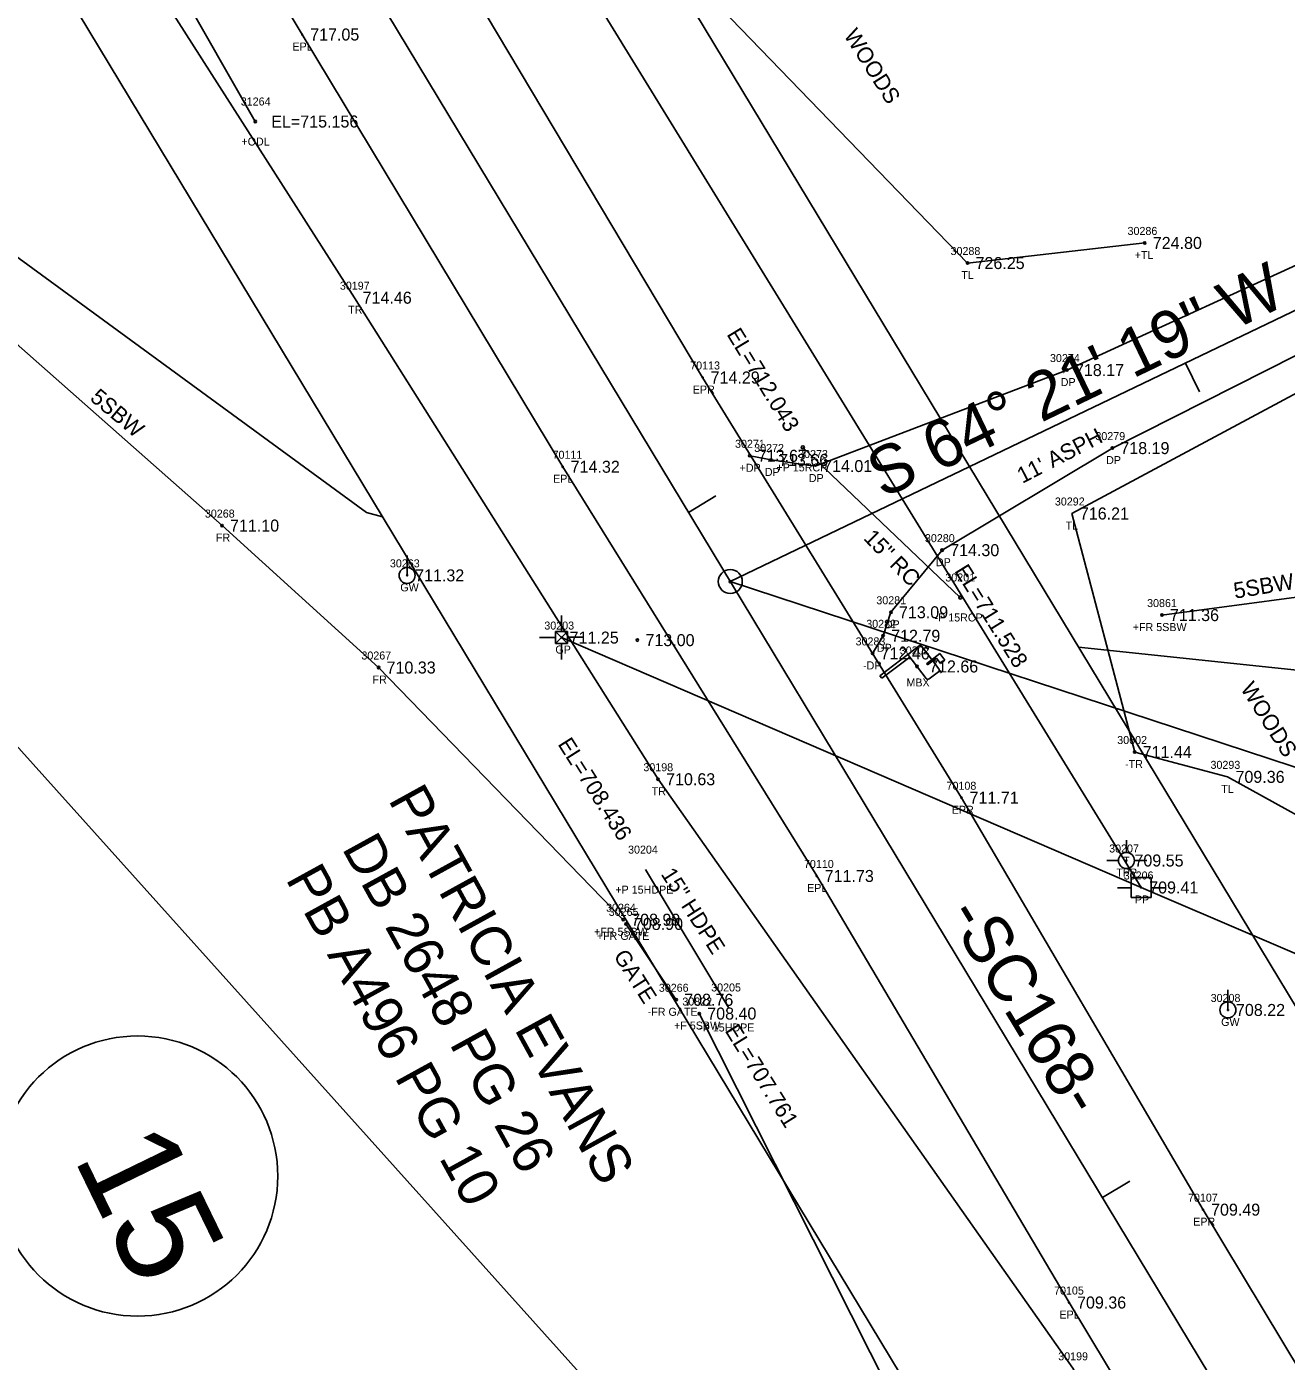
# Model space of a CAD drawing. Extents: x 1375131 to 1378678, y 999028 to 1004053.
# Drawn here: x 1377107.8 to 1377265.2, y 1001844.5 to 1002011.2 of the extents above; entities that cross this region are included whole.
import ezdxf

# ---------------------------------------------------------------- set-up
doc = ezdxf.new("R2010")
doc.units = 0
for name, color, linetype in [('RD_EX_BldgApp', 7, 'Continuous'), ('RD_EX_BldgApp_txCode', 7, 'Continuous'), ('RD_EX_DR_Pipe', 7, 'Continuous'), ('RD_EX_DR_Pipe_txCode', 7, 'Continuous'), ('RD_EX_Driveway', 7, 'Continuous'), ('RD_EX_Driveway_txCode', 7, 'Continuous'), ('RD_EX_DV_Prop', 7, 'Continuous'), ('RD_EX_DV_TX_Prop(Owner ID)', 7, 'Continuous'), ('RD_EX_Fence_Other', 7, 'Continuous'), ('RD_EX_Fence_Other_txCode', 7, 'Continuous'), ('RD_EX_H2O', 7, 'Continuous'), ('RD_EX_H2O_txCode', 7, 'Continuous'), ('RD_EX_Road', 7, 'Continuous'), ('RD_EX_Road_txCode', 7, 'Continuous'), ('RD_EX_RW', 7, 'Continuous'), ('RD_EX_SU_Elec', 7, 'Continuous'), ('RD_EX_TX_BldgApp_ELEV', 7, 'Continuous'), ('RD_EX_TX_Driveway_ELEV', 7, 'Continuous'), ('RD_EX_TX_Fence_Other_ELEV', 7, 'Continuous'), ('RD_EX_TX_H2O_ELEV', 7, 'Continuous'), ('RD_EX_TX_Road_ELEV', 7, 'Continuous'), ('RD_EX_TX_UT_ELEV', 7, 'Continuous'), ('RD_EX_TX_VEG_ELEV', 7, 'Continuous'), ('RD_EX_UT', 7, 'Continuous'), ('RD_EX_UT_txCode', 7, 'Continuous'), ('RD_EX_VEG', 7, 'Continuous'), ('RD_EX_VEG_txCode', 7, 'Continuous'), ('RD_HC_Cl', 7, 'Continuous'), ('RD_HC_Data', 7, 'Continuous'), ('RD_HC_Data_Tic', 7, 'Continuous'), ('RD_HC_Survey_ELEV', 7, 'Continuous'), ('RD_SMD_Locator', 7, 'Continuous'), ('RD_TX_Drainage', 7, 'Continuous'), ('RD_TX_Misc2', 7, 'Continuous'), ('RD_TX_Pipe_ElevEX', 7, 'Continuous')]:
    doc.layers.add(name, color=color, linetype=linetype)

msp = doc.modelspace()

# ---------------------------------------------------------------- linework, layer by layer
at = {"layer": 'RD_EX_BldgApp'}
for p, q in [((1377217.91, 1001932.77), (1377214.39, 1001930.11)), ((1377217.91, 1001932.77), (1377219.3, 1001933.82)), ((1377220.19, 1001929.75), (1377217.91, 1001932.77)), ((1377219.65, 1001933.77), (1377221.78, 1001930.95)), ((1377220.22, 1001931.6), (1377221.89, 1001932.87)), ((1377221.89, 1001932.87), (1377222.51, 1001932.05)), ((1377218.16, 1001932.43), (1377214.64, 1001929.78)), ((1377220.33, 1001931.45), (1377220.22, 1001931.6)), ((1377221.47, 1001932.31), (1377220.33, 1001931.45)), ((1377221.97, 1001931.64), (1377221.47, 1001932.31)), ((1377222.51, 1001932.05), (1377221.97, 1001931.64)), ((1377214.39, 1001930.11), (1377214.64, 1001929.78)), ((1377221.73, 1001930.6), (1377220.54, 1001929.7)), ((1377221.73, 1001930.6), (1377221.93, 1001930.75)), ((1377221.93, 1001930.75), (1377222.08, 1001930.56)), ((1377222.08, 1001930.56), (1377221.98, 1001930.48))]:
    msp.add_line(p, q, dxfattribs=at)
for centre, start, end in [((1377219.45, 1001933.62), 37.0668, 127.0668), ((1377221.58, 1001930.8), 307.0668, 37.0668), ((1377220.39, 1001929.9), 217.0668, 307.0668)]:
    msp.add_arc(centre, 0.25, start, end, dxfattribs=at)
at = {"layer": 'RD_EX_DR_Pipe'}
for p, q in [((1377204.78, 1001958.63), (1377224.45, 1001939.88)), ((1377185.11, 1001905.88), (1377195.49, 1001888.66))]:
    msp.add_line(p, q, dxfattribs=at)
at = {"layer": 'RD_EX_Driveway'}
for points in [[(1377198.42, 1001957.52), (1377200.81, 1001957.06), (1377206.31, 1001956.3), (1377237.77, 1001968.29), (1377271.95, 1001983.94), (1377310.88, 1002003.15)], [(1377315.4, 1001995.58), (1377274.11, 1001974.03), (1377243.44, 1001958.54), (1377222.18, 1001945.79), (1377215.79, 1001938.03), (1377214.81, 1001935.09), (1377213.5, 1001932.9)]]:
    msp.add_lwpolyline(points, dxfattribs=at)
at = {"layer": 'RD_EX_DV_Prop'}
msp.add_line((1376947.76, 1002098.6), (1377150.28, 1001950.48), dxfattribs=at)
for points in [[(1377150.28, 1001950.48), (1377152.29, 1001949.95)], [(1377239.22, 1001933.68), (1377316.8, 1001925.5), (1377415.78, 1001865), (1377549.86, 1001831.61)]]:
    msp.add_lwpolyline(points, dxfattribs=at)
at = {"layer": 'RD_EX_DV_TX_Prop(Owner ID)'}
msp.add_circle((1377121.69, 1001867.6), 17.5, dxfattribs=at)
at = {"layer": 'RD_EX_Fence_Other'}
msp.add_line((1377182.68, 1001899.1), (1377188.96, 1001889.62), dxfattribs=at)
for points in [[(1377491.06, 1002061.52), (1377478.6, 1002062.15), (1377445.25, 1002038.31), (1377440.22, 1002014.81), (1377436.73, 1001992.25), (1377399.99, 1001998.37), (1377304.37, 1001966.22), (1377283.11, 1001947.94), (1377275.82, 1001941.17), (1377249.63, 1001937.68)], [(1377182.34, 1001899.62), (1377151.78, 1001931.13), (1377132.23, 1001948.86), (1377093.24, 1001983.33), (1377067.17, 1002003.69)], [(1377191.84, 1001887.9), (1377236.93, 1001798.52), (1377265.75, 1001745.48), (1377304.79, 1001682.79)]]:
    msp.add_lwpolyline(points, dxfattribs=at)
at = {"layer": 'RD_EX_H2O'}
msp.add_lwpolyline([(1377136.38, 1001999.34), (1377116.95, 1002033.41), (1377090.35, 1002075.98), (1377065.42, 1002117.59), (1377038.3, 1002163.03), (1377017.87, 1002196.37), (1376989.72, 1002244.93), (1376963.62, 1002288.23), (1376935.26, 1002334.03)], dxfattribs=at)
at = {"layer": 'RD_EX_Road'}
for points in [[(1377350.34, 1001708.26), (1377317.92, 1001758.89), (1377286.96, 1001809.89), (1377254.77, 1001863.4), (1377224.6, 1001914.86), (1377192.26, 1001967.36), (1377160.97, 1002019.84), (1377129.72, 1002070.66), (1377099.39, 1002121.71), (1377064.16, 1002179.08), (1377033.49, 1002231.09), (1377014.7, 1002262.97), (1377013.31, 1002264.91)], [(1377330.92, 1001696.38), (1377301.06, 1001747.92), (1377269.09, 1001800.22), (1377238.03, 1001851.8), (1377206.51, 1001905.09), (1377174.78, 1001956.21), (1377142.24, 1002010.21), (1377112.37, 1002059.86), (1377081.07, 1002112.14), (1377047.75, 1002166.27), (1377015.04, 1002220.7), (1376995.39, 1002252.52), (1376994.75, 1002253.91)]]:
    msp.add_lwpolyline(points, dxfattribs=at)
at = {"layer": 'RD_EX_RW'}
for p, q in [((1377036.35, 1002269.57), (1377580.54, 1001368.57)), ((1376979.85, 1002235.45), (1377524.04, 1001334.45))]:
    msp.add_line(p, q, dxfattribs=at)
at = {"layer": 'RD_EX_SU_Elec'}
for points in [[(1376932.6, 1002329.07), (1377163.28, 1002039.96), (1377247.04, 1001903.65)], [(1377174.65, 1001934.87), (1377247.04, 1001903.65), (1377437.44, 1001822.1), (1377567.31, 1002066.68)]]:
    msp.add_lwpolyline(points, dxfattribs=at)
at = {"layer": 'RD_EX_UT'}
for p, q in [((1377155.35, 1001942.64), (1377155.35, 1001945.14)), ((1377174.65, 1001935.62), (1377174.65, 1001937.62)), ((1377173.88, 1001934.9), (1377171.88, 1001934.9)), ((1377175.4, 1001935.62), (1377173.9, 1001934.12)), ((1377173.9, 1001935.62), (1377175.4, 1001934.12)), ((1377175.4, 1001935.62), (1377173.9, 1001935.62)), ((1377173.9, 1001935.62), (1377173.9, 1001934.12)), ((1377175.4, 1001934.12), (1377175.4, 1001935.62)), ((1377175.4, 1001934.91), (1377177.41, 1001934.91)), ((1377173.9, 1001934.12), (1377175.4, 1001934.12)), ((1377174.65, 1001934.12), (1377174.65, 1001932.12)), ((1377245.2, 1001909.55), (1377245.2, 1001908.02)), ((1377242.74, 1001907.03), (1377244.2, 1001907.03)), ((1377246.2, 1001907.03), (1377247.74, 1001907.03)), ((1377248.29, 1001904.9), (1377245.79, 1001904.9)), ((1377245.79, 1001904.9), (1377245.79, 1001902.4)), ((1377248.29, 1001902.4), (1377248.29, 1001904.9)), ((1377244.07, 1001903.62), (1377245.81, 1001903.62)), ((1377248.25, 1001903.62), (1377250.07, 1001903.62)), ((1377245.79, 1001902.4), (1377248.29, 1001902.4)), ((1377257.88, 1001888.35), (1377257.88, 1001890.85))]:
    msp.add_line(p, q, dxfattribs=at)
for centre in [(1377155.35, 1001942.64), (1377245.2, 1001907.02), (1377257.88, 1001888.35)]:
    msp.add_circle(centre, 1, dxfattribs=at)
at = {"layer": 'RD_EX_VEG'}
for points in [[(1377227.27, 1001786.89), (1377002.39, 1002037.45), (1376937.65, 1002151.76), (1376893.73, 1002289.53), (1376925.29, 1002323.56)], [(1376925.29, 1002323.56), (1376964.39, 1002271.55), (1376999.6, 1002220.98), (1377033.75, 1002161.52), (1377072.45, 1002098.21), (1377110.65, 1002037.08), (1377148.79, 1001977.33), (1377186.7, 1001917.17), (1377238.51, 1001843.58), (1377265.98, 1001789.91), (1377290.89, 1001746.87), (1377322.19, 1001689.75), (1377357.87, 1001632.38)], [(1377534.01, 1002073.13), (1377547.87, 1002047.96), (1377449.99, 1001867.71), (1377414.83, 1001847.8), (1377322.94, 1001881.51), (1377257.82, 1001917.47), (1377246.23, 1001920.57)], [(1377200.2, 1002035.7), (1377185.96, 1002022.4), (1377225.35, 1001981.66), (1377247.49, 1001984.17)], [(1377293.69, 1001980), (1377238.38, 1001950.37), (1377246.23, 1001920.57)]]:
    msp.add_lwpolyline(points, dxfattribs=at)
at = {"layer": 'RD_HC_Cl'}
for p, q in [((1377008.1, 1002252.51), (1377552.29, 1001351.51)), ((1377284.22, 1001984.36), (1377195.72, 1001941.87))]:
    msp.add_line(p, q, dxfattribs=at)
at = {"layer": 'RD_HC_Data'}
msp.add_line((1377195.72, 1001941.87), (1377336.15, 1001895.74), dxfattribs=at)
for radius in [1.5, 0.141]:
    msp.add_circle((1377195.72, 1001941.87), radius, dxfattribs=at)
at = {"layer": 'RD_HC_Data_Tic'}
for p, q in [((1377252.58, 1001969.17), (1377254.32, 1001965.56)), ((1377190.51, 1001950.5), (1377193.93, 1001952.57)), ((1377242.21, 1001864.9), (1377245.63, 1001866.97))]:
    msp.add_line(p, q, dxfattribs=at)
at = {"layer": 'RD_SMD_Locator'}
for centre, radius in [((1377142.24, 1002010.21), 0.075), ((1377136.38, 1001999.34), 0.15), ((1377247.49, 1001984.17), 0.15), ((1377225.35, 1001981.66), 0.15), ((1377237.77, 1001968.29), 0.15), ((1377192.26, 1001967.36), 0.075), ((1377198.15, 1001957.58), 0.15), ((1377204.78, 1001958.63), 0.2), ((1377243.44, 1001958.54), 0.15), ((1377174.78, 1001956.21), 0.075), ((1377200.81, 1001957.06), 0.15), ((1377132.23, 1001948.86), 0.15), ((1377222.18, 1001945.79), 0.15), ((1377155.35, 1001942.64), 0.075), ((1377195.72, 1001941.87), 0.075), ((1377224.45, 1001939.88), 0.2), ((1377215.79, 1001938.03), 0.15), ((1377249.63, 1001937.68), 0.15), ((1377174.65, 1001934.87), 0.075), ((1377184.12, 1001934.55), 0.15), ((1377214.81, 1001935.09), 0.15), ((1377213.49, 1001932.89), 0.15), ((1377151.78, 1001931.13), 0.15), ((1377219.05, 1001931.26), 0.15), ((1377246.23, 1001920.57), 0.15), ((1377186.7, 1001917.17), 0.15), ((1377224.6, 1001914.86), 0.075), ((1377245.2, 1001907.02), 0.075), ((1377206.51, 1001905.09), 0.075), ((1377247.04, 1001903.65), 0.075), ((1377182.34, 1001899.62), 0.15), ((1377182.68, 1001899.1), 0.15), ((1377188.96, 1001889.62), 0.15), ((1377191.84, 1001887.9), 0.15), ((1377257.88, 1001888.35), 0.075), ((1377254.77, 1001863.4), 0.075), ((1377238.03, 1001851.8), 0.075)]:
    msp.add_circle(centre, radius, dxfattribs=at)

# ---------------------------------------------------------------- texts
at = {"layer": 'RD_EX_BldgApp_txCode'}
for s, p in [('30202', (1377216.89, 1001932.76)), ('MBX', (1377217.72, 1001928.76))]:
    msp.add_text(s, height=1, dxfattribs=at).set_placement(p)
at = {"layer": 'RD_EX_DR_Pipe_txCode'}
for s, p in [('+P 15RCP', (1377201.48, 1001955.63)), ('30201', (1377222.58, 1001941.88)), ('-P 15RCP', (1377221.23, 1001936.88)), ('30204', (1377182.95, 1001907.88)), ('+P 15HDPE', (1377181.36, 1001902.88)), ('30205', (1377193.33, 1001890.66)), ('-P 15HDPE', (1377191.82, 1001885.66))]:
    msp.add_text(s, height=1, dxfattribs=at).set_placement(p)
at = {"layer": 'RD_EX_Driveway_txCode'}
for s, p in [('30274', (1377235.65, 1001969.29)), ('DP', (1377236.99, 1001966.29)), ('30271', (1377196.31, 1001958.58)), ('30279', (1377241.32, 1001959.54)), ('30272', (1377198.7, 1001958.06)), ('30273', (1377204.19, 1001957.3)), ('DP', (1377242.66, 1001956.54)), ('+DP', (1377196.88, 1001955.58)), ('DP', (1377200.03, 1001955.06)), ('DP', (1377205.53, 1001954.3)), ('30280', (1377220.03, 1001946.79)), ('DP', (1377221.4, 1001943.79)), ('30281', (1377213.96, 1001939.03)), ('30282', (1377212.7, 1001936.09)), ('DP', (1377215.01, 1001936.03)), ('30283', (1377211.37, 1001933.89)), ('DP', (1377214.03, 1001933.09)), ('-DP', (1377212.3, 1001930.89))]:
    msp.add_text(s, height=1, dxfattribs=at).set_placement(p)
at = {"layer": 'RD_EX_DV_TX_Prop(Owner ID)'}
for s, height, rotation, p in [('PATRICIA EVANS', 5, 298.8091, (1377152.92, 1001914.63)), ('DB 2648 PG 26', 5, 298.8091, (1377147.13, 1001908.57)), ('PB A496 PG 10', 5, 298.8091, (1377140.11, 1001904.73)), ('15', 12.5, 295.9191, (1377113.62, 1001869.91))]:
    msp.add_text(s, height=height, rotation=rotation, dxfattribs=at).set_placement(p)
at = {"layer": 'RD_EX_Fence_Other_txCode'}
for s, p in [('30268', (1377130.09, 1001949.86)), ('FR', (1377131.47, 1001946.86)), ('30861', (1377247.78, 1001938.68)), ('30861', (1377247.78, 1001938.68)), ('+FR 5SBW', (1377245.99, 1001935.68)), ('+FR 5SBW', (1377245.99, 1001935.68)), ('30267', (1377149.64, 1001932.13)), ('FR', (1377151.02, 1001929.13)), ('30264', (1377180.2, 1001900.62)), ('30265', (1377180.53, 1001900.1)), ('+FR 5SBW', (1377178.7, 1001897.62)), ('+FR GATE', (1377179.04, 1001897.1)), ('30266', (1377186.79, 1001890.62)), ('30822', (1377189.73, 1001888.9)), ('-FR GATE', (1377185.4, 1001887.62)), ('+F 5SBW', (1377188.69, 1001885.9))]:
    msp.add_text(s, height=1, dxfattribs=at).set_placement(p)
at = {"layer": 'RD_EX_H2O_txCode'}
for s, p in [('31264', (1377134.57, 1002001.34)), ('+ODL', (1377134.65, 1001996.34))]:
    msp.add_text(s, height=1, dxfattribs=at).set_placement(p)
at = {"layer": 'RD_EX_Road_txCode'}
for s, p in [('EPL', (1377141.03, 1002008.21)), ('70113', (1377190.71, 1001968.36)), ('EPR', (1377191.03, 1001965.36)), ('70111', (1377173.52, 1001957.21)), ('EPL', (1377173.58, 1001954.21)), ('70108', (1377222.73, 1001915.86)), ('EPR', (1377223.38, 1001912.86)), ('70110', (1377204.92, 1001906.09)), ('EPL', (1377205.31, 1001903.09)), ('70107', (1377252.89, 1001864.4)), ('EPR', (1377253.54, 1001861.4)), ('70105', (1377236.16, 1001852.8)), ('EPL', (1377236.83, 1001849.8))]:
    msp.add_text(s, height=1, dxfattribs=at).set_placement(p)
at = {"layer": 'RD_EX_TX_BldgApp_ELEV'}
msp.add_text('712.66', height=1.5, dxfattribs=at).set_placement((1377220.55, 1001930.51))
at = {"layer": 'RD_EX_TX_Driveway_ELEV'}
for s, p in [('718.17', (1377238.77, 1001967.54)), ('718.19', (1377244.44, 1001957.79)), ('713.67', (1377199.15, 1001956.83)), ('713.66', (1377201.81, 1001956.31)), ('714.01', (1377207.31, 1001955.55)), ('714.30', (1377223.18, 1001945.04)), ('713.09', (1377216.79, 1001937.28)), ('712.79', (1377215.81, 1001934.34)), ('712.46', (1377214.49, 1001932.14))]:
    msp.add_text(s, height=1.5, dxfattribs=at).set_placement(p)
at = {"layer": 'RD_EX_TX_Fence_Other_ELEV'}
for s, p in [('711.10', (1377133.23, 1001948.11)), ('711.36', (1377250.63, 1001936.93)), ('711.36', (1377250.63, 1001936.93)), ('713.00', (1377185.12, 1001933.8)), ('710.33', (1377152.78, 1001930.38)), ('708.99', (1377183.34, 1001898.87)), ('708.90', (1377183.68, 1001898.35)), ('708.76', (1377189.96, 1001888.87)), ('708.40', (1377192.84, 1001887.15))]:
    msp.add_text(s, height=1.5, dxfattribs=at).set_placement(p)
at = {"layer": 'RD_EX_TX_H2O_ELEV'}
msp.add_text('EL=715.156', height=1.5, dxfattribs=at).set_placement((1377138.38, 1001998.59))
at = {"layer": 'RD_EX_TX_Road_ELEV'}
for s, p in [('717.05', (1377143.24, 1002009.46)), ('714.29', (1377193.26, 1001966.61)), ('714.32', (1377175.78, 1001955.46)), ('711.71', (1377225.6, 1001914.11)), ('711.73', (1377207.51, 1001904.34)), ('709.49', (1377255.77, 1001862.65)), ('709.36', (1377239.03, 1001851.05))]:
    msp.add_text(s, height=1.5, dxfattribs=at).set_placement(p)
at = {"layer": 'RD_EX_TX_UT_ELEV'}
for s, p in [('711.32', (1377156.35, 1001941.89)), ('711.25', (1377175.65, 1001934.12)), ('709.55', (1377246.2, 1001906.27)), ('708.22', (1377258.88, 1001887.6)), ('708.22', (1377258.88, 1001887.6))]:
    msp.add_text(s, height=1.5, dxfattribs=at).set_placement(p)
at = {"layer": 'RD_EX_TX_VEG_ELEV'}
for s, p in [('724.80', (1377248.49, 1001983.42)), ('726.25', (1377226.35, 1001980.91)), ('714.46', (1377149.79, 1001976.58)), ('716.21', (1377239.38, 1001949.62)), ('711.44', (1377247.23, 1001919.82)), ('711.44', (1377247.23, 1001919.82)), ('710.63', (1377187.7, 1001916.42)), ('709.36', (1377258.82, 1001916.72))]:
    msp.add_text(s, height=1.5, dxfattribs=at).set_placement(p)
at = {"layer": 'RD_EX_UT'}
msp.add_text('T', height=1, dxfattribs=at).set_placement((1377244.78, 1001906.5))
at = {"layer": 'RD_EX_UT_txCode'}
for s, p in [('30263', (1377153.2, 1001943.64)), ('GW', (1377154.5, 1001940.64)), ('30203', (1377172.49, 1001935.87)), ('GP', (1377173.87, 1001932.87)), ('30207', (1377243.04, 1001908.02)), ('TPP', (1377243.93, 1001905.02)), ('30206', (1377244.86, 1001904.65)), ('PP', (1377246.26, 1001901.65)), ('30208', (1377255.72, 1001889.35)), ('30208', (1377255.72, 1001889.35)), ('GW', (1377257.03, 1001886.35)), ('GW', (1377257.03, 1001886.35))]:
    msp.add_text(s, height=1, dxfattribs=at).set_placement(p)
at = {"layer": 'RD_EX_VEG_txCode'}
for s, p in [('30286', (1377245.34, 1001985.17)), ('30288', (1377223.23, 1001982.66)), ('+TL', (1377246.23, 1001982.17)), ('30197', (1377146.95, 1001978.33)), ('TL', (1377224.58, 1001979.66)), ('TR', (1377147.99, 1001975.33)), ('30292', (1377236.26, 1001951.37)), ('TL', (1377237.6, 1001948.37)), ('30602', (1377244.05, 1001921.57)), ('30602', (1377244.05, 1001921.57)), ('30198', (1377184.86, 1001918.17)), ('-TR', (1377245.03, 1001918.57)), ('-TR', (1377245.03, 1001918.57)), ('30293', (1377255.7, 1001918.47)), ('TR', (1377185.9, 1001915.17)), ('TL', (1377257.04, 1001915.47)), ('30199', (1377236.68, 1001844.58))]:
    msp.add_text(s, height=1, dxfattribs=at).set_placement(p)
at = {"layer": 'RD_HC_Data'}
for s, rotation, p in [('S 64%%d 21\' 19" W', 25.6446, (1377214.75, 1001952.2)), ('-SC168-', 301.1312, (1377222.64, 1001900.27))]:
    msp.add_text(s, height=6, rotation=rotation, dxfattribs=at).set_placement(p)
at = {"layer": 'RD_HC_Survey_ELEV'}
msp.add_text('709.41', height=1.5, dxfattribs=at).set_placement((1377248.04, 1001902.9))
at = {"layer": 'RD_TX_Drainage'}
for s, rotation, p in [('15" RC', 314.3347, (1377212.24, 1001947.21)), ('15" HDPE', 302.6377, (1377186.99, 1001905.31))]:
    msp.add_text(s, height=2, rotation=rotation, dxfattribs=at).set_placement(p)
at = {"layer": 'RD_TX_Misc2'}
for s, rotation, p in [('WOODS', 302.3586, (1377209.83, 1002010.12)), ('5SBW', 319.929, (1377115.62, 1001964.61)), ("11' ASPH", 27.3477, (1377232.2, 1001954.07)), ('5SBW', 9.3459, (1377258.76, 1001939.72)), ('WOODS', 302.3586, (1377259.38, 1001928.51)), ('GATE', 302.3586, (1377181.07, 1001895.1))]:
    msp.add_text(s, height=2, rotation=rotation, dxfattribs=at).set_placement(p)
at = {"layer": 'RD_TX_Pipe_ElevEX'}
for s, rotation, p in [('EL=712.043', 301.3216, (1377195.21, 1001972.76)), ('EL=711.528', 301.8237, (1377223.66, 1001943.21)), ('EL=708.436', 302.3037, (1377174.11, 1001921.56)), ('EL=707.761', 301.8788, (1377194.98, 1001885.76))]:
    msp.add_text(s, height=2, rotation=rotation, dxfattribs=at).set_placement(p)

doc.saveas('drawing.dxf')
